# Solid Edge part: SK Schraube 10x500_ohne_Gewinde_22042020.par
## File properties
Author: fknapp
Template: Normal.par
Last saved by: fknapp
Revision: 32
Application: Solid Edge
Username: fknapp
Material: Aluminium
Genauigkeit: 0,99
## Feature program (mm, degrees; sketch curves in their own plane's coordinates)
sketch for "unnamed RevolvedProtrusion 1" plane through (0, 0, 0) normal (0, 0, 1) x-axis (1, 0, 0)
  line (0, 54) -> (9, 54)
  line (9, 54) -> (9, 53)
  line (9, 53) -> (5, 49)
  line (5, 49) -> (5, 46.3)
  line (5, 46.3) -> (4.7548, 46.3)
  arc centre (4.7548, 44.6952) radius 1.6048 from (4.7548, 46.3) to (3.15, 44.6952) ccw
  line (3.15, 44.6952) -> (3.15, 42)
  line (3.15, 42) -> (5, 42)
  line (5, -433) -> (5, 42)
  line (0.5, -446) -> (5, -433)
  line (0, -446) -> (0.5, -446)
revolve "unnamed RevolvedProtrusion 1" add full turn 360 deg about sketch line (0, 54) -> (0, -446)
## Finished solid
Body 1: solid body, 11 faces, 10 edges, 0 vertices.
  Faces by surface: cylinder 4, plane 4, cone 2, torus 1
  Edges by curve: circle 10
Bounding box of the edges (mm; curved faces can reach further): 18.000 x 500.000 x 18.000, from (-9, -446, -9) to (9, 54, 9).
Cylindrical faces by radius (mm): R3.15 x1, R5 x2, R9 x1
Conical faces (half-angle, radius in mm at the cone's reference point): 19.0935 deg R5 x1, 45 deg R9 x1
Toroidal faces (ring radius, tube radius in mm): R4.7548 r1.6048 x1
Planar faces by outward normal: +y 2, -y 2
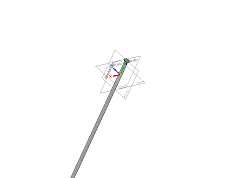
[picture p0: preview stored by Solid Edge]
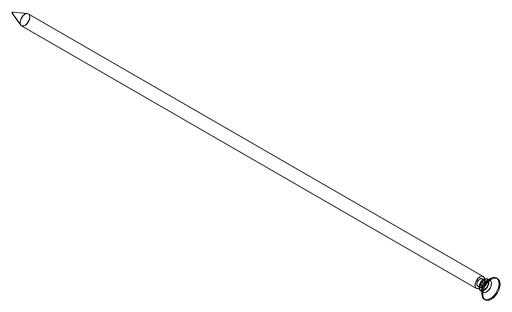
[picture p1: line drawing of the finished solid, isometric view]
